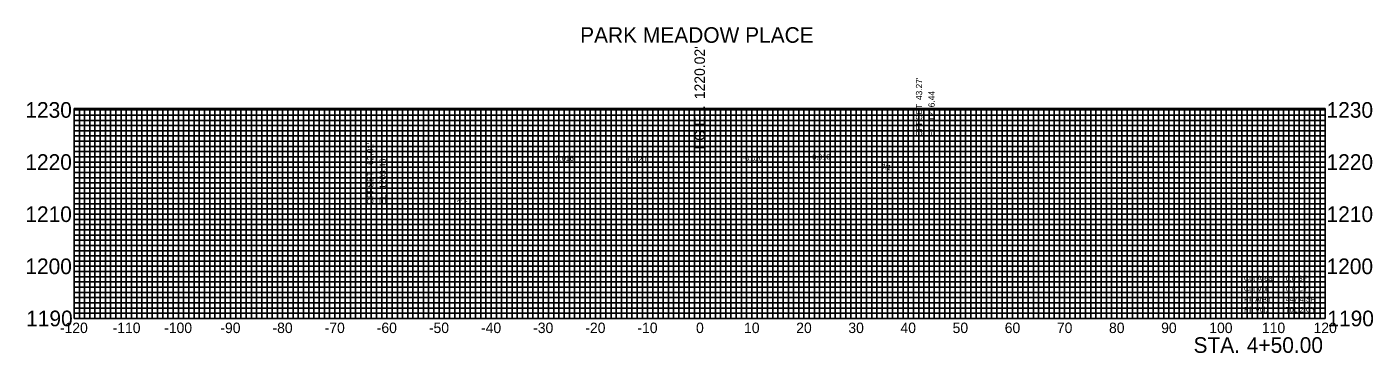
# Model space of a CAD drawing. Extents: x -129 to 129, y 1183 to 1246.
import ezdxf

# ---------------------------------------------------------------- set-up
doc = ezdxf.new("R2010")
doc.units = 0
for name, color, linetype in [('DES - SHEET - Light Grid', 7, 'Continuous'), ('DES - SHEET - Linework', 7, 'Continuous'), ('DES - XS - Proposed - Finished Grade Slopes Text', 7, 'Continuous'), ('DES - XS - Proposed - Text', 7, 'Continuous')]:
    doc.layers.add(name, color=color, linetype=linetype)

msp = doc.modelspace()

# ---------------------------------------------------------------- linework, layer by layer
at = {"layer": 'DES - SHEET - Light Grid'}
for p, q in [((-119, 1190), (-119, 1230.26)), ((-118, 1190), (-118, 1230.26)), ((-117, 1190), (-117, 1230.26)), ((-116, 1190), (-116, 1230.26)), ((-115, 1190), (-115, 1230.26)), ((-114, 1190), (-114, 1230.26)), ((-113, 1190), (-113, 1230.26)), ((-112, 1190), (-112, 1230.26)), ((-111, 1190), (-111, 1230.26)), ((-109, 1190), (-109, 1230.26)), ((-108, 1190), (-108, 1230.26)), ((-107, 1190), (-107, 1230.26)), ((-106, 1190), (-106, 1230.26)), ((-105, 1190), (-105, 1230.26)), ((-104, 1190), (-104, 1230.26)), ((-103, 1190), (-103, 1230.26)), ((-102, 1190), (-102, 1230.26)), ((-101, 1190), (-101, 1230.26)), ((-99, 1190), (-99, 1230.26)), ((-98, 1190), (-98, 1230.26)), ((-97, 1190), (-97, 1230.26)), ((-96, 1190), (-96, 1230.26)), ((-95, 1190), (-95, 1230.26)), ((-94, 1190), (-94, 1230.26)), ((-93, 1190), (-93, 1230.26)), ((-92, 1190), (-92, 1230.26)), ((-91, 1190), (-91, 1230.26)), ((-89, 1190), (-89, 1230.26)), ((-88, 1190), (-88, 1230.26)), ((-87, 1190), (-87, 1230.26)), ((-86, 1190), (-86, 1230.26)), ((-85, 1190), (-85, 1230.26)), ((-84, 1190), (-84, 1230.26)), ((-83, 1190), (-83, 1230.26)), ((-82, 1190), (-82, 1230.26)), ((-81, 1190), (-81, 1230.26)), ((-79, 1190), (-79, 1230.26)), ((-78, 1190), (-78, 1230.26)), ((-77, 1190), (-77, 1230.26)), ((-76, 1190), (-76, 1230.26)), ((-75, 1190), (-75, 1230.26)), ((-74, 1190), (-74, 1230.26)), ((-73, 1190), (-73, 1230.26)), ((-72, 1190), (-72, 1230.26)), ((-71, 1190), (-71, 1230.26)), ((-69, 1190), (-69, 1230.26)), ((-68, 1190), (-68, 1230.26)), ((-67, 1190), (-67, 1230.26)), ((-66, 1190), (-66, 1230.26)), ((-65, 1190), (-65, 1230.26)), ((-64, 1190), (-64, 1230.26)), ((-63, 1190), (-63, 1230.26)), ((-62, 1190), (-62, 1230.26)), ((-61, 1190), (-61, 1230.26)), ((-59, 1190), (-59, 1230.26)), ((-58, 1190), (-58, 1230.26)), ((-57, 1190), (-57, 1230.26)), ((-56, 1190), (-56, 1230.26)), ((-55, 1190), (-55, 1230.26)), ((-54, 1190), (-54, 1230.26)), ((-53, 1190), (-53, 1230.26)), ((-52, 1190), (-52, 1230.26)), ((-51, 1190), (-51, 1230.26)), ((-49, 1190), (-49, 1230.26)), ((-48, 1190), (-48, 1230.26)), ((-47, 1190), (-47, 1230.26)), ((-46, 1190), (-46, 1230.26)), ((-45, 1190), (-45, 1230.26)), ((-44, 1190), (-44, 1230.26)), ((-43, 1190), (-43, 1230.26)), ((-42, 1190), (-42, 1230.26)), ((-41, 1190), (-41, 1230.26)), ((-39, 1190), (-39, 1230.26)), ((-38, 1190), (-38, 1230.26)), ((-37, 1190), (-37, 1230.26)), ((-36, 1190), (-36, 1230.26)), ((-35, 1190), (-35, 1230.26)), ((-34, 1190), (-34, 1230.26)), ((-33, 1190), (-33, 1230.26)), ((-32, 1190), (-32, 1230.26)), ((-31, 1190), (-31, 1230.26)), ((-29, 1190), (-29, 1230.26)), ((-28, 1190), (-28, 1230.26)), ((-27, 1190), (-27, 1230.26)), ((-26, 1190), (-26, 1230.26)), ((-25, 1190), (-25, 1230.26)), ((-24, 1190), (-24, 1230.26)), ((-23, 1190), (-23, 1230.26)), ((-22, 1190), (-22, 1230.26)), ((-21, 1190), (-21, 1230.26)), ((-19, 1190), (-19, 1230.26)), ((-18, 1190), (-18, 1230.26)), ((-17, 1190), (-17, 1230.26)), ((-16, 1190), (-16, 1230.26)), ((-15, 1190), (-15, 1230.26)), ((-14, 1190), (-14, 1230.26)), ((-13, 1190), (-13, 1230.26)), ((-12, 1190), (-12, 1230.26)), ((-11, 1190), (-11, 1230.26)), ((-9, 1190), (-9, 1230.26)), ((-8, 1190), (-8, 1230.26)), ((-7, 1190), (-7, 1230.26)), ((-6, 1190), (-6, 1230.26)), ((-5, 1190), (-5, 1230.26)), ((-4, 1190), (-4, 1230.26)), ((-3, 1190), (-3, 1230.26)), ((-2, 1190), (-2, 1230.26)), ((-1, 1190), (-1, 1230.26)), ((1, 1190), (1, 1230.26)), ((2, 1190), (2, 1230.26)), ((3, 1190), (3, 1230.26)), ((4, 1190), (4, 1230.26)), ((5, 1190), (5, 1230.26)), ((6, 1190), (6, 1230.26)), ((7, 1190), (7, 1230.26)), ((8, 1190), (8, 1230.26)), ((9, 1190), (9, 1230.26)), ((11, 1190), (11, 1230.26)), ((12, 1190), (12, 1230.26)), ((13, 1190), (13, 1230.26)), ((14, 1190), (14, 1230.26)), ((15, 1190), (15, 1230.26)), ((16, 1190), (16, 1230.26)), ((17, 1190), (17, 1230.26)), ((18, 1190), (18, 1230.26)), ((19, 1190), (19, 1230.26)), ((21, 1190), (21, 1230.26)), ((22, 1190), (22, 1230.26)), ((23, 1190), (23, 1230.26)), ((24, 1190), (24, 1230.26)), ((25, 1190), (25, 1230.26)), ((26, 1190), (26, 1230.26)), ((27, 1190), (27, 1230.26)), ((28, 1190), (28, 1230.26)), ((29, 1190), (29, 1230.26)), ((31, 1190), (31, 1230.26)), ((32, 1190), (32, 1230.26)), ((33, 1190), (33, 1230.26)), ((34, 1190), (34, 1230.26)), ((35, 1190), (35, 1230.26)), ((36, 1190), (36, 1230.26)), ((37, 1190), (37, 1230.26)), ((38, 1190), (38, 1230.26)), ((39, 1190), (39, 1230.26)), ((41, 1190), (41, 1230.26)), ((42, 1190), (42, 1230.26)), ((43, 1190), (43, 1230.26)), ((44, 1190), (44, 1230.26)), ((45, 1190), (45, 1230.26)), ((46, 1190), (46, 1230.26)), ((47, 1190), (47, 1230.26)), ((48, 1190), (48, 1230.26)), ((49, 1190), (49, 1230.26)), ((51, 1190), (51, 1230.26)), ((52, 1190), (52, 1230.26)), ((53, 1190), (53, 1230.26)), ((54, 1190), (54, 1230.26)), ((55, 1190), (55, 1230.26)), ((56, 1190), (56, 1230.26)), ((57, 1190), (57, 1230.26)), ((58, 1190), (58, 1230.26)), ((59, 1190), (59, 1230.26)), ((61, 1190), (61, 1230.26)), ((62, 1190), (62, 1230.26)), ((63, 1190), (63, 1230.26)), ((64, 1190), (64, 1230.26)), ((65, 1190), (65, 1230.26)), ((66, 1190), (66, 1230.26)), ((67, 1190), (67, 1230.26)), ((68, 1190), (68, 1230.26)), ((69, 1190), (69, 1230.26)), ((71, 1190), (71, 1230.26)), ((72, 1190), (72, 1230.26)), ((73, 1190), (73, 1230.26)), ((74, 1190), (74, 1230.26)), ((75, 1190), (75, 1230.26)), ((76, 1190), (76, 1230.26)), ((77, 1190), (77, 1230.26)), ((78, 1190), (78, 1230.26)), ((79, 1190), (79, 1230.26)), ((81, 1190), (81, 1230.26)), ((82, 1190), (82, 1230.26)), ((83, 1190), (83, 1230.26)), ((84, 1190), (84, 1230.26)), ((85, 1190), (85, 1230.26)), ((86, 1190), (86, 1230.26)), ((87, 1190), (87, 1230.26)), ((88, 1190), (88, 1230.26)), ((89, 1190), (89, 1230.26)), ((91, 1190), (91, 1230.26)), ((92, 1190), (92, 1230.26)), ((93, 1190), (93, 1230.26)), ((94, 1190), (94, 1230.26)), ((95, 1190), (95, 1230.26)), ((96, 1190), (96, 1230.26)), ((97, 1190), (97, 1230.26)), ((98, 1190), (98, 1230.26)), ((99, 1190), (99, 1230.26)), ((101, 1190), (101, 1230.26)), ((102, 1190), (102, 1230.26)), ((103, 1190), (103, 1230.26)), ((104, 1190), (104, 1230.26)), ((105, 1190), (105, 1230.26)), ((106, 1190), (106, 1230.26)), ((107, 1190), (107, 1230.26)), ((108, 1190), (108, 1230.26)), ((109, 1190), (109, 1230.26)), ((111, 1190), (111, 1230.26)), ((112, 1190), (112, 1230.26)), ((113, 1190), (113, 1230.26)), ((114, 1190), (114, 1230.26)), ((115, 1190), (115, 1230.26)), ((116, 1190), (116, 1230.26)), ((117, 1190), (117, 1230.26)), ((118, 1190), (118, 1230.26)), ((119, 1190), (119, 1230.26)), ((-120, 1229), (120, 1229)), ((-120, 1228), (120, 1228)), ((-120, 1227), (120, 1227)), ((-120, 1226), (120, 1226)), ((-120, 1225), (120, 1225)), ((-120, 1224), (120, 1224)), ((-120, 1223), (120, 1223)), ((-120, 1222), (120, 1222)), ((-120, 1221), (120, 1221)), ((-120, 1219), (120, 1219)), ((-120, 1218), (120, 1218)), ((-120, 1217), (120, 1217)), ((-120, 1216), (120, 1216)), ((-120, 1215), (120, 1215)), ((-120, 1214), (120, 1214)), ((-120, 1213), (120, 1213)), ((-120, 1212), (120, 1212)), ((-120, 1211), (120, 1211)), ((-120, 1209), (120, 1209)), ((-120, 1208), (120, 1208)), ((-120, 1207), (120, 1207)), ((-120, 1206), (120, 1206)), ((-120, 1205), (120, 1205)), ((-120, 1204), (120, 1204)), ((-120, 1203), (120, 1203)), ((-120, 1202), (120, 1202)), ((-120, 1201), (120, 1201)), ((-120, 1199), (120, 1199)), ((-120, 1198), (120, 1198)), ((-120, 1197), (120, 1197)), ((-120, 1196), (120, 1196)), ((-120, 1195), (120, 1195)), ((-120, 1194), (120, 1194)), ((-120, 1193), (120, 1193)), ((-120, 1192), (120, 1192)), ((-120, 1191), (120, 1191))]:
    msp.add_line(p, q, dxfattribs=at)
at = {"layer": 'DES - SHEET - Linework'}
for p, q in [((-120, 1230.26), (120, 1230.26)), ((-120, 1190), (-120, 1230.26)), ((-120, 1230), (120, 1230)), ((-110, 1190), (-110, 1230.26)), ((-100, 1190), (-100, 1230.26)), ((-90, 1190), (-90, 1230.26)), ((-80, 1190), (-80, 1230.26)), ((-70, 1190), (-70, 1230.26)), ((-60, 1190), (-60, 1230.26)), ((-50, 1190), (-50, 1230.26)), ((-40, 1190), (-40, 1230.26)), ((-30, 1190), (-30, 1230.26)), ((-20, 1190), (-20, 1230.26)), ((-10, 1190), (-10, 1230.26)), ((0, 1190), (0, 1230.26)), ((10, 1190), (10, 1230.26)), ((20, 1190), (20, 1230.26)), ((30, 1190), (30, 1230.26)), ((40, 1190), (40, 1230.26)), ((50, 1190), (50, 1230.26)), ((60, 1190), (60, 1230.26)), ((70, 1190), (70, 1230.26)), ((80, 1190), (80, 1230.26)), ((90, 1190), (90, 1230.26)), ((100, 1190), (100, 1230.26)), ((110, 1190), (110, 1230.26)), ((120, 1190), (120, 1230.26)), ((-120, 1220), (120, 1220)), ((-120, 1210), (120, 1210)), ((-120, 1200), (120, 1200)), ((-120, 1190), (120, 1190))]:
    msp.add_line(p, q, dxfattribs=at)

# ---------------------------------------------------------------- texts
at = {"layer": 'DES - XS - Proposed - Finished Grade Slopes Text'}
for s, height, rotation, p in [("43.27'", 1.2, 90, (42.67, 1231.89)), ('1216.44', 1.2, 90, (45.07, 1227.82)), ('OFFSET ', 1.2, 90, (42.67, 1224.84)), ('EL. ', 1.2, 90, (45.07, 1224.84)), ("-62.01'", 1.2, 90, (-62.61, 1218.91)), ('0.016', 1, 0.9282, (21.59, 1220.46)), ('1203.46', 1.2, 90, (-60.21, 1214.84)), ('0.016', 1, 359.1065, (-27.61, 1220.26)), ('-0.020', 1, 1.1693, (-14.18, 1219.98)), ('-0.020', 1, 358.8789, (8.24, 1220.23)), ('4:1', 1, 346.1145, (34.73, 1218.85)), ('OFFSET ', 1.2, 90, (-62.61, 1211.86)), ('EL. ', 1.2, 90, (-60.21, 1211.86)), ('2:1', 1, 26.5166, (-46.2, 1211.64))]:
    msp.add_text(s, height=height, rotation=rotation, dxfattribs=at).set_placement(p)
at = {"layer": 'DES - XS - Proposed - Text'}
for s, height, p in [('PARK MEADOW PLACE', 3, (-22.94, 1242.87)), ('1230', 3, (-129.36, 1228.5)), ('1230', 3, (120.24, 1228.5)), ('1220', 3, (-129.36, 1218.5)), ('1220', 3, (120.24, 1218.5)), ('1210', 3, (-129.36, 1208.5)), ('1210', 3, (120.24, 1208.5)), ('1200', 3, (-129.36, 1198.5)), ('1200', 3, (120.24, 1198.5)), ('Cut Area', 1, (104.4, 1197.2)), ('Cut Area', 1, (104.4, 1197.2)), ('0.0', 1, (112.4, 1197.2)), ('0.0', 1, (112.4, 1197.2)), (' SF', 1, (114.34, 1197.2)), (' SF', 1, (114.34, 1197.2)), ('Cut Vol.', 1, (104.4, 1195.2)), ('Cut Vol.', 1, (104.4, 1195.2)), ('0.0', 1, (112.4, 1195.2)), ('0.0', 1, (112.4, 1195.2)), (' CY', 1, (114.34, 1195.2)), (' CY', 1, (114.34, 1195.2)), ('Fill Area', 1, (104.4, 1193.2)), ('Fill Area', 1, (104.4, 1193.2)), ('447.4', 1, (112.4, 1193.2)), ('447.4', 1, (112.4, 1193.2)), (' SF', 1, (115.89, 1193.2)), (' SF', 1, (115.89, 1193.2)), ('1190', 3, (-129.2, 1188.5)), ('Fill Vol.', 1, (104.4, 1191.2)), ('Fill Vol.', 1, (104.4, 1191.2)), ('701.2', 1, (112.4, 1191.2)), ('701.2', 1, (112.4, 1191.2)), (' CY', 1, (115.89, 1191.2)), (' CY', 1, (115.89, 1191.2)), ('1190', 3, (120.4, 1188.5)), ('-120', 2, (-122.73, 1187.2)), ('-110', 2, (-112.62, 1187.2)), ('-100', 2, (-102.73, 1187.2)), ('-90', 2, (-91.95, 1187.2)), ('-80', 2, (-81.95, 1187.2)), ('-70', 2, (-71.95, 1187.2)), ('-60', 2, (-61.95, 1187.2)), ('-50', 2, (-51.95, 1187.2)), ('-40', 2, (-41.95, 1187.2)), ('-30', 2, (-31.95, 1187.2)), ('-20', 2, (-21.95, 1187.2)), ('-10', 2, (-11.95, 1187.2)), ('0', 2, (-0.71, 1187.2)), ('10', 2, (8.51, 1187.2)), ('20', 2, (18.51, 1187.2)), ('30', 2, (28.51, 1187.2)), ('40', 2, (38.51, 1187.2)), ('50', 2, (48.51, 1187.2)), ('60', 2, (58.51, 1187.2)), ('70', 2, (68.51, 1187.2)), ('80', 2, (78.51, 1187.2)), ('90', 2, (88.51, 1187.2)), ('100', 2, (97.74, 1187.2)), ('110', 2, (107.84, 1187.2)), ('120', 2, (117.74, 1187.2)), (' STA. ', 3, (93.61, 1183.4)), ('4+50.00', 3, (104.94, 1183.4))]:
    msp.add_text(s, height=height, dxfattribs=at).set_placement(p)
for s, p in [("1220.02'", (1, 1232.05)), ('FG EL. ', (1, 1222.42))]:
    msp.add_text(s, height=2, rotation=90, dxfattribs=at).set_placement(p)

doc.saveas('drawing.dxf')
